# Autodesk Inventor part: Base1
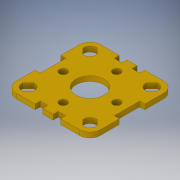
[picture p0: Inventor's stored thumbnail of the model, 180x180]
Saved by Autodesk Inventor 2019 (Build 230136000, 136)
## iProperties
Created: 2019-04
Part Number: Base1
Material: Generic
Document SubType Name: Modeling
Designer: Plo
Density: 1 g/cm^3
Appearance: Gold
Author: Plo
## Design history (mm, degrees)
sketch "Sketch1"
  geometry: L1 (16.5, 12.5)-(16.5, 6.5); L2 (16.5, -12.5)-(16.5, -6.5); L3 (16.5, 5)-(14.5, 5); L4 (14.5, 5)-(14.5, -5); L5 (5, -16.5)-(5, -14.5); L6 (-16.5, -5)-(-14.5, -5); L7 (-14.5, -5)-(-14.5, 5); L8 (-5, 16.5)-(-5, 14.5); L9 (5, 14.5)-(5, 16.5); L10 (16.5, 5)-(14.5, 5); L11 (16.5, -5)-(14.5, -5); L12 (5, -16.5)-(5, -14.5); L13 (-5, -16.5)-(-5, -14.5); L14 (-5, 14.5)-(-5, 16.5); L15 (-14.5, 5)-(-16.5, 5); L16 (-14.5, -5)-(-16.5, -5); L17 (16.5, 12.5)-(16.5, 5); L18 (16.5, -5)-(16.5, -12.5); L19 (12.5, -16.5)-(5, -16.5); L20 (-5, -16.5)-(-12.5, -16.5); L21 (-12.5, 16.5)-(-5, 16.5); L22 (5, 16.5)-(12.5, 16.5); L23 (-16.5, -12.5)-(-16.5, -5); L24 (-16.5, 5)-(-16.5, 12.5); L25 (14.5, 0)-(10.5, 0); L26 (-14.5, 0)-(-10.5, 0); L27 (2, -14.5)-(2, -16.5); L28 (2, -16.5)-(-2, -16.5); L29 (-2, -16.5)-(-2, -14.5); L30 (0, 16.5)-(2, 16.5); L31 (2, 16.5)-(2, 14.5); L32 (5, -14.5)-(2, -14.5); L33 (-2, -14.5)-(-5, -14.5); L34 (0, 16.5)-(-2, 16.5); L35 (-2, 16.5)-(-2, 14.5); L36 (-5, 14.5)-(-2, 14.5); L37 (2, 14.5)-(5, 14.5); L38 (16.5, 16.5)-(15.328, 15.328); L39 (13.914, 13.914)-(-16.5, -16.5); L40 (13.561, 10.732)-(12.5, 9.672); L41 (13.561, 10.732)-(14.621, 11.793); L42 (10.732, 13.561)-(11.793, 14.621); L43 (10.732, 13.561)-(9.672, 12.5); L44 (13.561, -10.732)-(14.621, -11.793); L45 (10.732, -13.561)-(9.672, -12.5); L46 (13.561, -10.732)-(12.5, -9.672); L47 (10.732, -13.561)-(11.793, -14.621); L48 (0, 16.5)-(0, 14.5); L49 (-13.561, 10.732)-(-12.5, 9.672); L50 (-10.732, 13.561)-(-9.672, 12.5); L51 (-10.732, 13.561)-(-11.793, 14.621); L52 (-13.561, 10.732)-(-14.621, 11.793); L53 (-13.561, -10.732)-(-12.5, -9.672); L54 (-10.732, -13.561)-(-9.672, -12.5); L55 (-10.732, -13.561)-(-11.793, -14.621); L56 (-13.561, -10.732)-(-14.621, -11.793); C1 r 1.5 at (10.5, 0); C2 r 1.5 at (-10.5, 0); C3 r 1.5 at (0, 10.5); C4 r 1.5 at (0, -10.5); C5 r 5.5 at (0, 0); A1 r 4 centre (12.5, -12.5) between (12.5, -16.5) and (16.5, -12.5); A2 r 4 centre (-12.5, -12.5) between (-16.5, -12.5) and (-12.5, -16.5); A3 r 4 centre (-12.5, 12.5) between (-12.5, 16.5) and (-16.5, 12.5); A4 r 4 centre (12.5, 12.5) between (16.5, 12.5) and (12.5, 16.5); A5 r 2.5 centre (12.146, 12.146) between (14.621, 11.793) and (11.793, 14.621); A6 r 2.5 centre (12.146, 12.146) between (9.672, 12.5) and (12.5, 9.672); A7 r 2.5 centre (12.146, -12.146) between (11.793, -14.621) and (14.621, -11.793); A8 r 2.5 centre (12.146, -12.146) between (12.5, -9.672) and (9.672, -12.5); A9 r 2.5 centre (-12.146, 12.146) between (-12.5, 9.672) and (-9.672, 12.5); A10 r 2.5 centre (-12.146, 12.146) between (-11.793, 14.621) and (-14.621, 11.793); A11 r 2.5 centre (-12.146, -12.146) between (-9.672, -12.5) and (-12.5, -9.672); A12 r 2.5 centre (-12.146, -12.146) between (-14.621, -11.793) and (-11.793, -14.621); 2 further points
  constraints: 112 end point, 33 perpendicular, 27 point on circle, 24 symmetric about line, 17 centre point, 11 point on line, 8 parallel, 8 tangent, 5 horizontal, 2 coincident, 2 midpoint, 1 vertical, 6 other
  dimensions: "d0" = 33 distance of point (16.5, -16.5) L39.end; "d1" = 33 distance of L38.start point (16.5, -16.5); "d18" = 4 radius of A1 (derived); "d19" = 4 radius of A2 (derived); "d20" = 4 radius of A3 (derived); "d21" = 4 radius of A4 (derived); "d23" = 3 diameter of C1
extrude "Extrusion2" new body sketch "Sketch1" distance "d38" = 2; taper "d39" = 0 deg
body "Solid2"
